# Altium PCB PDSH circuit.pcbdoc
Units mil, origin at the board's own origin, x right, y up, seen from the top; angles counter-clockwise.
Board outline 2980 x 2587.24 mil, 4 copper layers (Top Layer, Mid-Layer 1, Mid-Layer 2, Bottom Layer); 30 components, 20 nets, 87 pads, 24 vias.
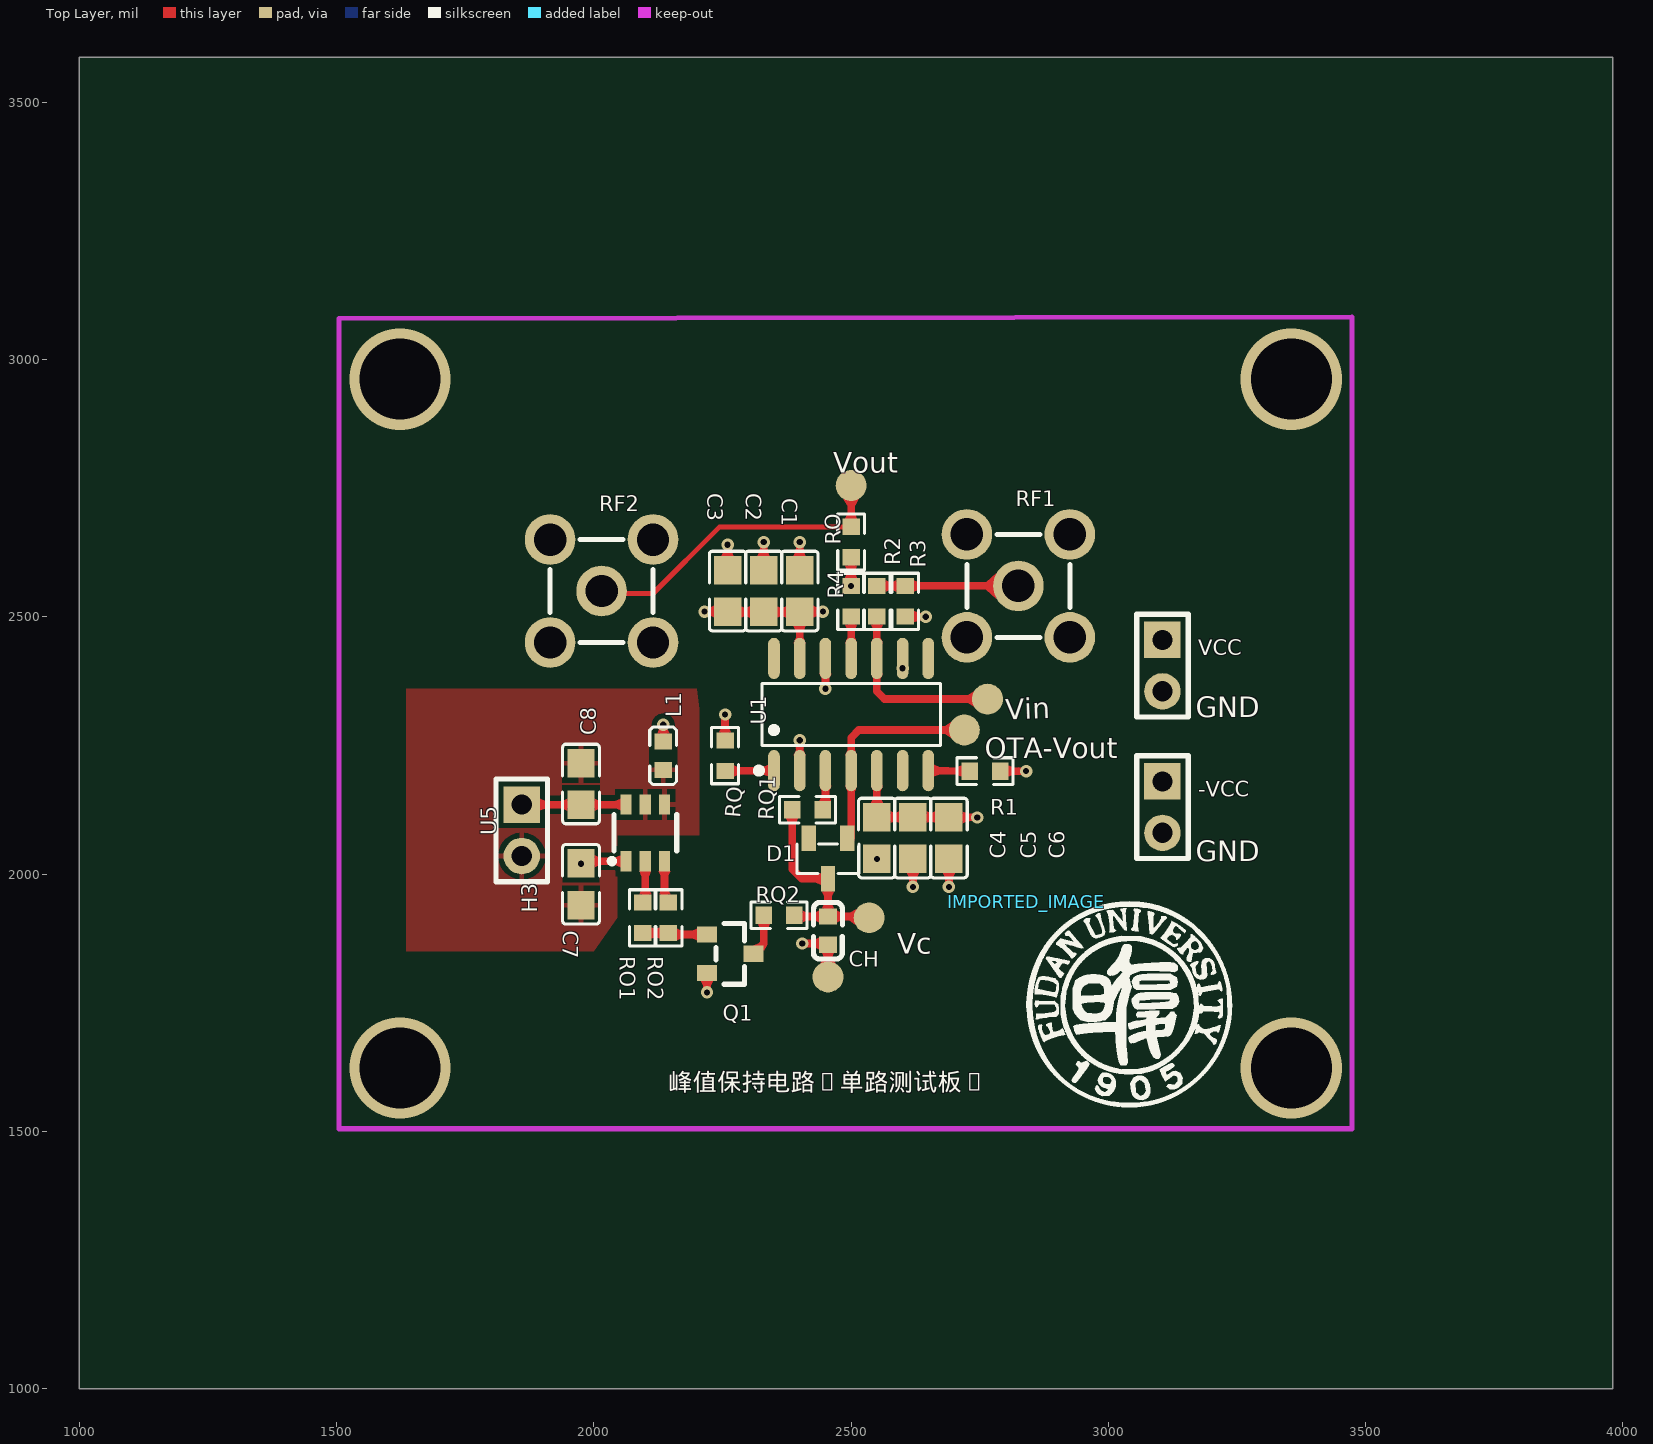
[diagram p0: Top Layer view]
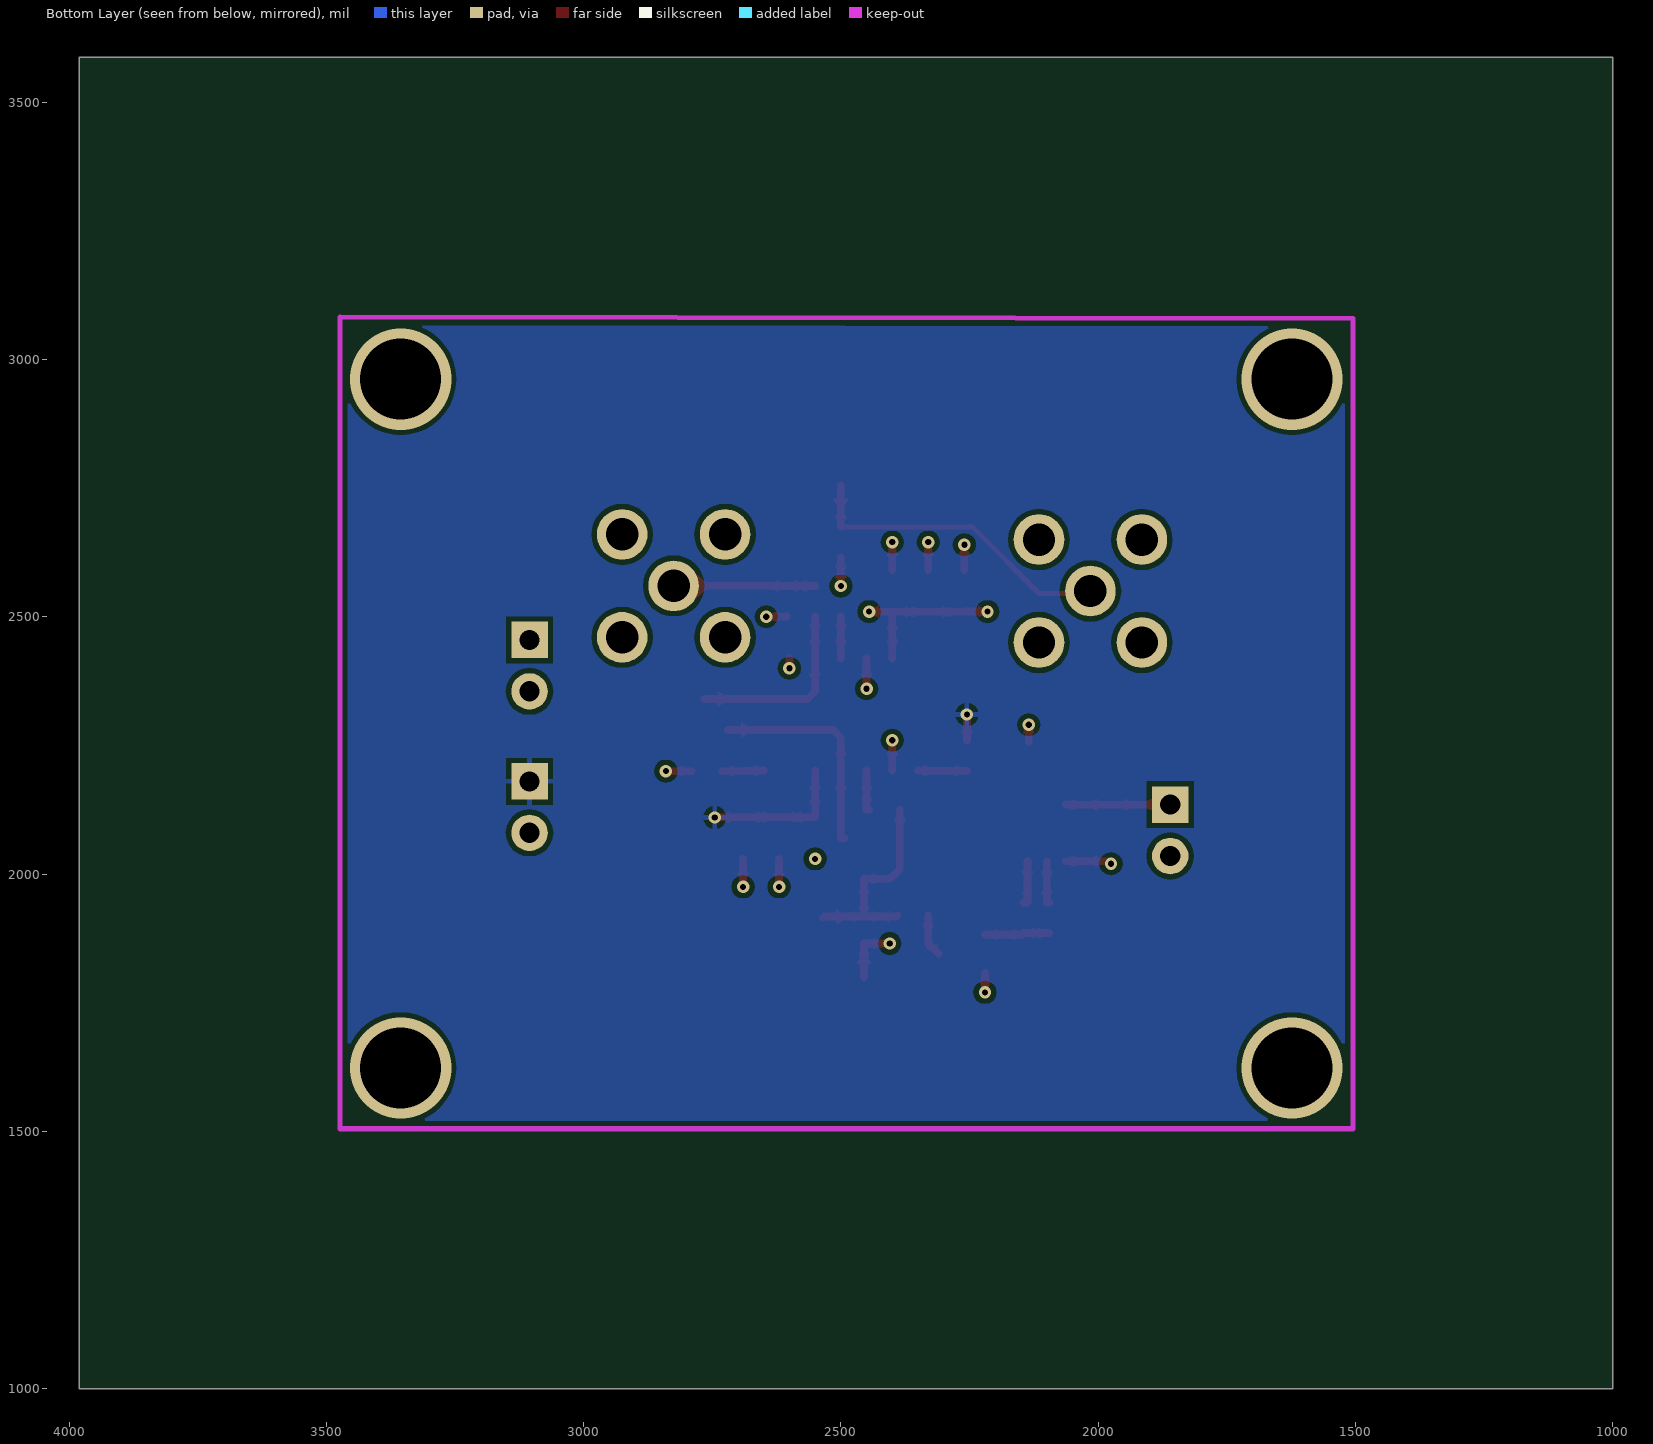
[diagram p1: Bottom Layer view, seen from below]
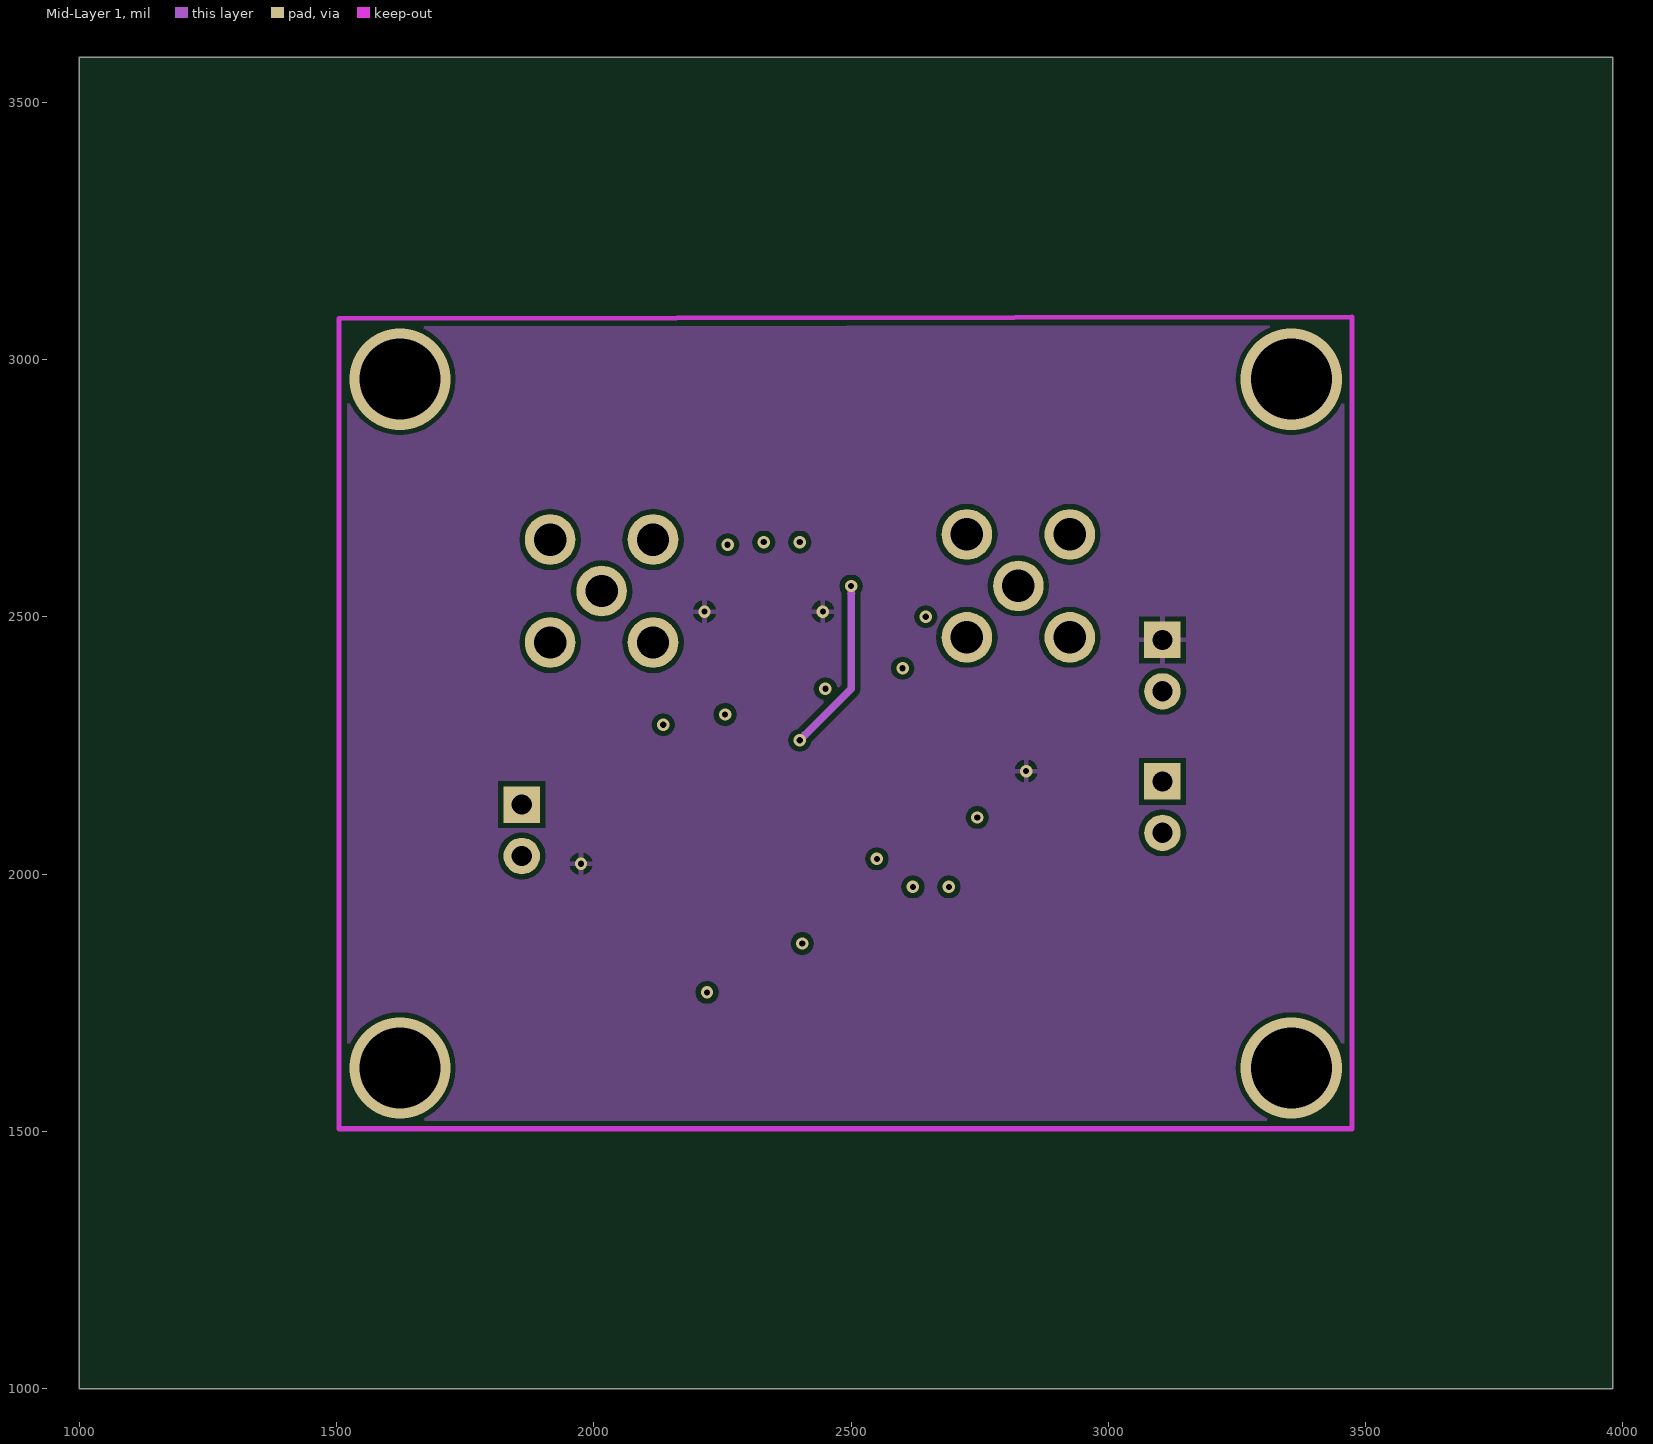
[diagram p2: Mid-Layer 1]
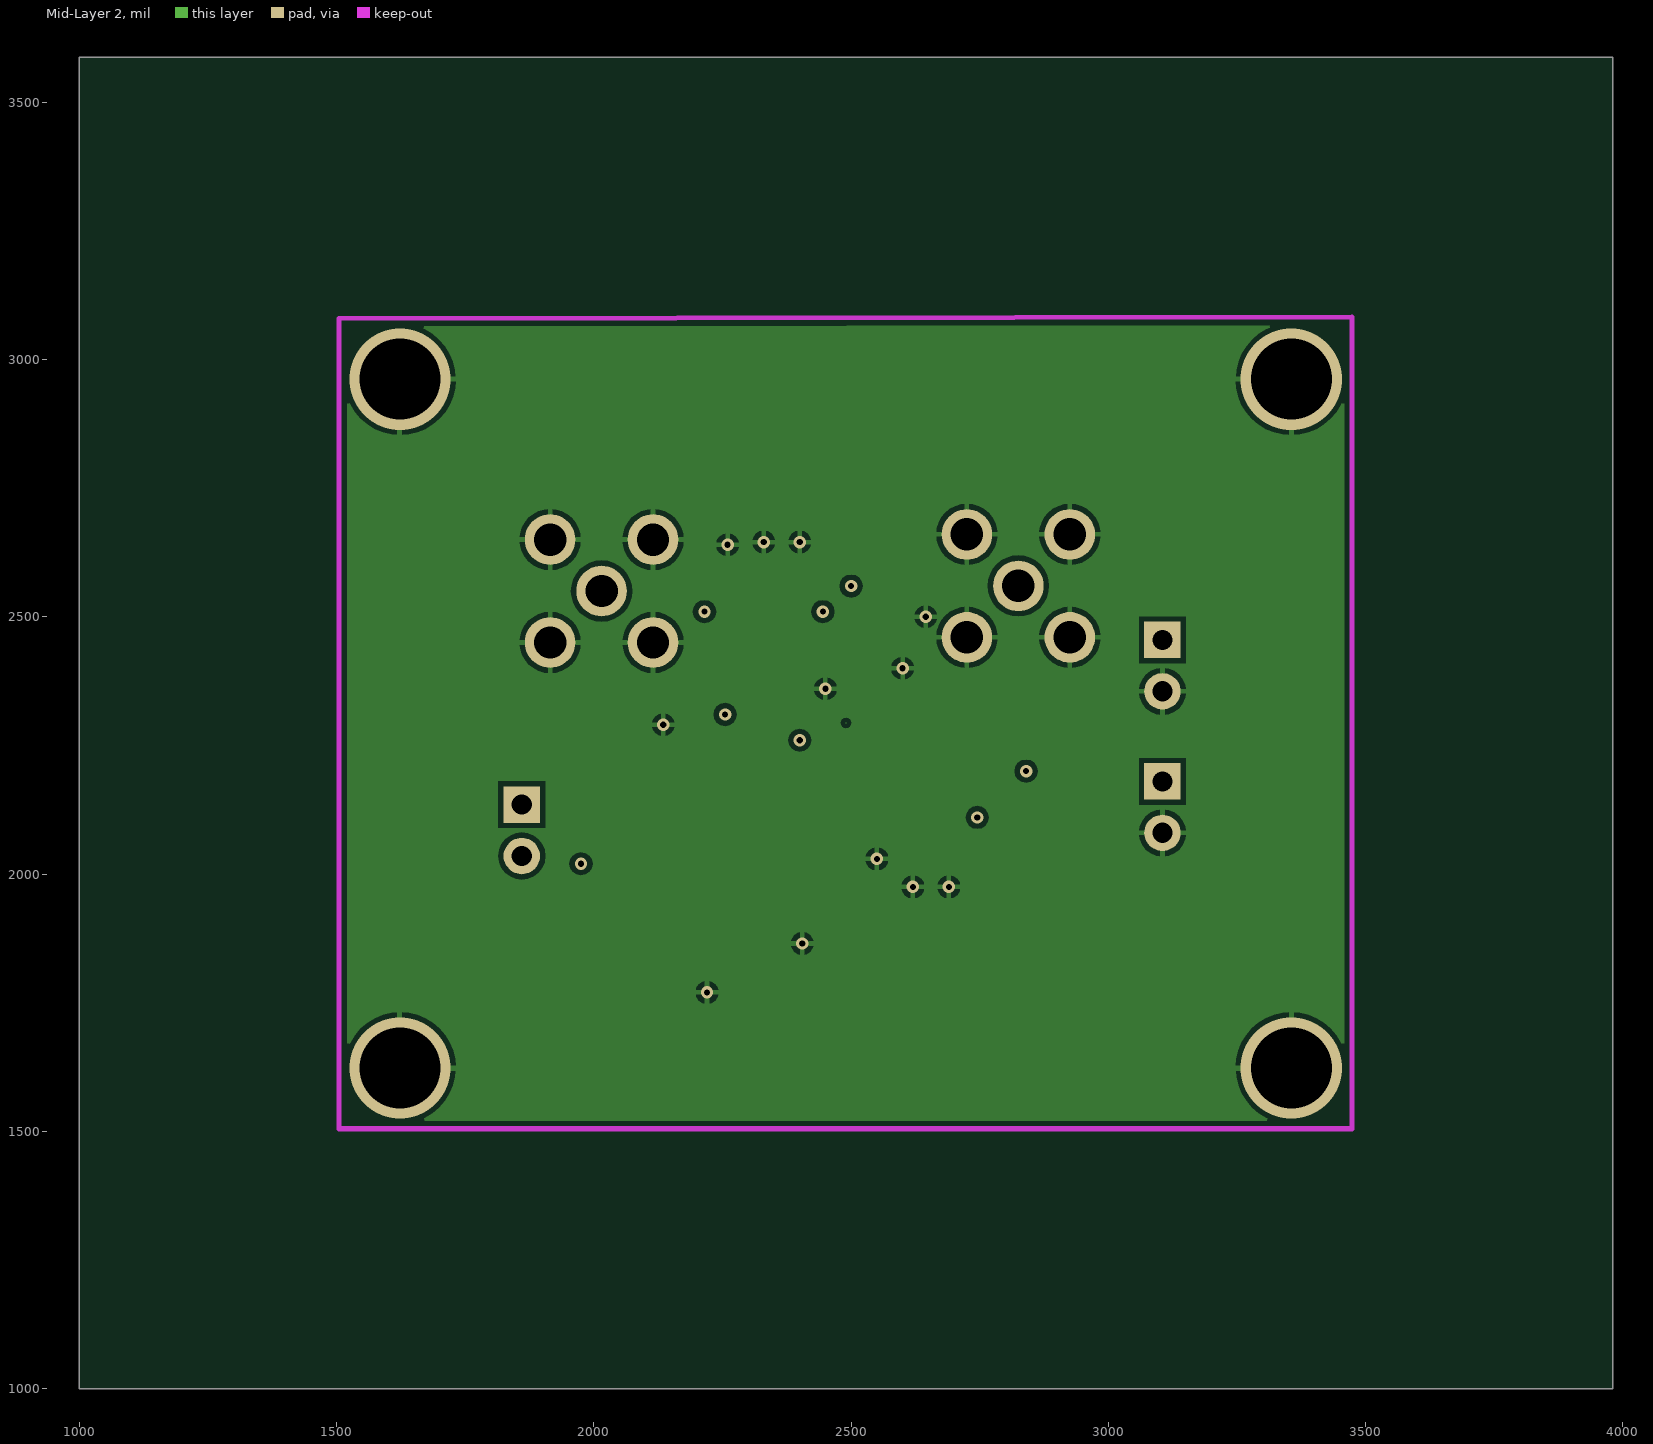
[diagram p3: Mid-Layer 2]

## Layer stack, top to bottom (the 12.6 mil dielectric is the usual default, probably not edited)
Top Solder: solder mask 0.4, Solder Resist, Dk 3.5
Top Layer: signal copper 1.4
Dielectric1: dielectric 12.6, FR-4, Dk 4.8
Mid-Layer 1: signal copper 1.4
Dielectric2: dielectric 12.6, FR-4, Dk 4.8
Mid-Layer 2: signal copper 1.4
Dielectric3: dielectric 12.6, FR-4, Dk 4.8
Bottom Layer: signal copper 1.4
Bottom Solder: solder mask 0.4, Solder Resist, Dk 3.5

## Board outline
3980,1000 1000,1000 1000,3587.24 3980,3587.24

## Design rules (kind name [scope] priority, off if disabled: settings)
Clearance [All] p1: gap=10 ignorepadtopadclearanceinfootprint=FALSE except(0: Arc-Hole Track-Hole SMDPad-Hole THPad-Hole Via-Hole Fill-Hole Poly-Hole Region-Hole Text-Hole)
PolygonConnect [All] p1: connectstyle=Relief reliefconductorwidth=10 reliefentries=4 polygonreliefangle="90 Angle" airgapwidth=10
RoutingVias [All] p1: holewidth=28 width=50 viastyle="Through Hole" minholewidth=28 minwidth=50 maxholewidth=28 maxwidth=50
SolderMaskExpansion [All] p1: expansion=4 istentingtop=FALSE
Width [All] p1: maxlimit=10 minlimit=10 preferedwidth=10
30 further rules are at their usual default settings.

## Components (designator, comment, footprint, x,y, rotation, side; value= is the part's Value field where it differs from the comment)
-VCC "Header-Male-2.54_1x2" HDR-TH_2P-P2.54-V-M-1 3105,2130 r270 top
C1 "2.2u" C0805 2400,2550 r270 top
C2 "10n" C0805 2330,2550 r270 top
C3 "470p" C0805 2260,2550 r270 top
C4 "470p" C0805 2550,2070 r90 top
C5 "10n" C0805 2620,2070 r90 top
C6 "2.2u" C0805 2690,2070 r90 top
C7 "2.2u" C0805 1975,1980 r270 top
C8 "470pF" C0805 1975,2175 r270 top
CH "47pF" C0603 2455,1890 r90 top
D1 "HSMS-2812-TR1G" SOT-23-3_L2.9-W1.3-P1.90-LS2.4-BR 2455,2030 r90 top
H3 "Header-Male-2.54_1x2" HDR-TH_2P-P2.54-V-M-1 1860,2085 r270 top
IMPORTED_IMAGE "Comment" IMPORTED_IMAGE 2840.18,1946.47 r0 top
L1 "UPZ1608U220-6R0TF" L0603 2135,2230 r90 top
Q1 "L2N7002LT1G" SOT-23_L2.9-W1.3-P1.90-LS2.4-BR 2265,1845 r180 top
R1 "330" R0603 2760,2200 r180 top
R2 "100" R0603 2550,2530 r90 top
R3 "50" R0603 2605,2530 r90 top
R4 "330" R0603 2500,2530 r90 top
RF1 "KH-SMA-KE-Z" SMA-TH_KH-SMA-KE-Z 2825,2560 r0 top
RF2 "KH-SMA-KE-Z" SMA-TH_KH-SMA-KE-Z 2015,2550 r0 top
RO "50" R0603 2500,2645 r270 top
RO1 "1k" R0603 2095,1915 r90 top
RO2 "1k" R0603 2145,1915 r90 top
RQ "300" R0603 2255,2230 r270 top
RQ1 "300" R0603 2415,2125 r0 top
RQ2 "50" R0603 2360,1920 r180 top
U1 "OPA615IDR" SOIC-14_L8.7-W3.9-P1.27-LS6.0-BL 2500,2310 r0 top
U5 "SL27511" SOT-23-6_L2.9-W1.6-P0.95-LS2.8-BR 2100,2080 r270 top
VCC "Header-Male-2.54_1x2" HDR-TH_2P-P2.54-V-M-1 3105,2405 r270 top

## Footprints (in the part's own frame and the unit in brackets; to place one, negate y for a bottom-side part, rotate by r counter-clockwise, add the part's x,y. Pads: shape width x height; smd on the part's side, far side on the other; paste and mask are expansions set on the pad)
C0603 [mm]
  rect 0.8x0.9 smd paste+0 mask+0.051: 1(-0.7,0) 2(0.7,0)
  silkscreen extent -1.41,-0.71 1.39,0.72
C0805 [mm]
  rect 1.41x1.35 smd paste-100 mask+0.051: 1(-1.03,0) 2(1.03,0)
  silkscreen extent -1.96,-0.9 1.96,0.9
HDR-TH_2P-P2.54-V-M-1 [mm]
  rect 1.8x1.8 hole 1 paste+0 mask+0.051: 1(-1.27,0)
  round 1.8 hole 1 paste+0 mask+0.051: 2(1.27,0)
  silkscreen extent -2.54,-1.27 2.54,1.27
IMPORTED_IMAGE [mil]
  silkscreen extent 0,-400 400,0
L0603 [mm]
  rect 0.8x0.864 smd paste-100 mask+0.051: 1(-0.7,0) 2(0.7,0)
  silkscreen extent -1.42,-0.65 1.41,0.67
R0603 [mil]
  rect 31.75x34.02 smd paste-3937.01 mask+2: 1(-29.66,0) 2(29.66,0)
  silkscreen extent -55,-26 55,26
SMA-TH_KH-SMA-KE-Z [mm]
  round 2.5 hole 1.6 paste+0 mask+0.051: 1(-2.54,-2.54) 2(-2.54,2.54) 3(2.54,2.54) 4(2.54,-2.54) 5(0,0)
  silkscreen extent -2.54,-2.54 2.54,2.54
SOIC-14_L8.7-W3.9-P1.27-LS6.0-BL [mil]
  oval 22.6x80.24 smd paste+0 mask+2: 1(-150,-109.02) 2(-100,-109.02) 3(-50,-109.02) 4(0,-109.02) 5(50,-109.02) 6(100,-109.02) 7(150,-109.02) 8(150,109.01) 9(100,109.01) 10(50,109.01) 11(0,109.01) 12(-50,109.01) 13(-100,109.01) 14(-150,109.01)
  silkscreen extent -185,-115 173,60
SOT-23-3_L2.9-W1.3-P1.90-LS2.4-BR [mm]
  rect 1.25x0.7 smd paste+0 mask+0.051: 1(1,-0.95) 2(1,0.95) 3(-1,0)
  silkscreen extent -0.73,-1.53 0.73,1.53
SOT-23-6_L2.9-W1.6-P0.95-LS2.8-BR [mm]
  rect 1x0.55 smd paste+0 mask+0.051: 1(1.4,-0.95) 2(1.4,0) 3(1.4,0.95) 4(-1.4,0.95) 5(-1.4,0) 6(-1.4,-0.95)
  silkscreen extent -0.9,-1.78 1.52,1.55
SOT-23_L2.9-W1.3-P1.90-LS2.4-BR [mm]
  rect 1x0.8 smd paste+0 mask+0.051: 1(1.15,-0.95) 2(1.15,0.95) 3(-1.15,0)
  silkscreen extent -0.7,-1.5 0.7,1.5

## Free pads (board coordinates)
  round 60 smd paste+0 mask+1.97: 1(2455,1800) 1(2500,2755) 1(2535,1915) 1(2720,2280) 1(2765,2340)

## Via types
v1: diameter 24, hole 12, Top Layer to Bottom Layer, 20 vias
v2: diameter 196.85, hole 157.48, Top Layer to Bottom Layer, 4 vias

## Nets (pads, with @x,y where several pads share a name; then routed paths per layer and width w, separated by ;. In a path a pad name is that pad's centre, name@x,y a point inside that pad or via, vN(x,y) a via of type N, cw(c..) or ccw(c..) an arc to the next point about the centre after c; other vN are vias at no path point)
-VCC: -VCC.1 C4.2 C5.2 C6.2 RQ.1 U1.5 | length 335.8
  Top Layer w15: RQ.1 v1(2255,2310) ; U1.5 2550,2110.5 2620,2110.5 2690,2110.5 v1(2745,2110)
AGND: C7.2 C8.1 H3.2 L1.1 U5.4 U5.5
D1_2: CH.2 D1.3 pad.1@2535,1915 RQ1.1 RQ2.1 | length 413.3
  Top Layer w15: RQ1.1 2385.3,2009.7 2404.4,1990.6 D1.3 CH.2 ; RQ2.1 2392.1,1917.6 CH.2 ; pad.1@2535,1915 2532.4,1917.6 CH.2
GND: -VCC.2 C1.1 C2.1 C3.1 C4.1 C5.1 C6.1 CH.1 L1.2 pad.1@2455,1800 Q1.2 R3.1 RF1.1 RF1.2 RF1.3 RF1.4 RF2.1 RF2.2 RF2.3 RF2.4 U1.9 U1.12 VCC.2 | length 570.5
  Top Layer w15: L1.2 v1(2135,2290) ; Q1.2 v1(2220,1770) ; C3.1@2260,2590.5 v1(2260,2640) ; C2.1@2330,2590.5 v1(2330,2645) ; C1.1@2400,2590.5 v1(2400,2645) ; v1(2405,1865) 2455,1865 CH.1 pad.1@2455,1800 ; v1(2450,2360) U1.12 ; v1(2600,2400) U1.9 ; R3.1 v1(2645,2500) ; v1(2620,1975) C5.1@2620,2029.5 ; v1(2690,1975) C6.1@2690,2029.5
  other v1: 2550,2029.45
  other v2: 1623.11,1623.11 3355.39,1623.11 1623.11,2961.69 3355.39,2961.69
Q1_3: Q1.3 RQ2.2 | length 83.3
  Top Layer w15: Q1.3 2330.3,1865.1 RQ2.2
RO_1: pad.1@2500,2755 RF2.5 RO.1 | length 621.1
  Top Layer w10: RF2.5 2020,2545 2115,2545 2244.7,2674.7 RO.1
  Top Layer w15: RO.1 pad.1@2500,2755
S$1077: 
U1_1: RQ.2 U1.1 | length 95
  Top Layer w15: RQ.2 U1.1
U1_7: R1.2 U1.7 | length 80.3
  Top Layer w15: U1.7 R1.2
U1_10: pad.1@2765,2340 R2.1 U1.10 | length 366.5
  Top Layer w15: R2.1 U1.10 2550,2355 2565,2340 2670,2340 pad.1@2765,2340
U1_11: R4.1 U1.11 | length 81.3
  Top Layer w15: U1.11 R4.1
U5_2: RO1.2 U5.2 | length 85.2
  Top Layer w15: RO1.2 2100,1944.7 U5.2
U5_3: RO2.2 U5.3 | length 87.8
  Top Layer w15: U5.3 2137.4,1944.7 RO2.2
VC: RQ1.2 U1.3 | length 81.3
  Top Layer w15: RQ1.2 2450,2125 U1.3
VCC: C1.2 C2.2 C3.2 C7.1 R1.1 U1.13 U5.1 VCC.1 | length 461
  Top Layer w15: v1(1975,2020) 1975,2020.5 1979.3,2024.9 U5.1 ; v1(2215,2510) 2259.5,2510 2260,2509.5 2330,2509.5 C1.2@2400,2509.5 ; U1.13 C1.2@2400,2509.5 ; v1(2445,2510) C1.2@2400,2509.5 ; R1.1 v1(2840,2200)
VCONTROL: Q1.1 RO1.1 RO2.1 | length 125.9
  Top Layer w15: RO1.1 RO2.1 2147.9,1882.4 Q1.1
VFB: R4.2 RO.2 U1.2 | length 455.7
  Top Layer w15: U1.2 v1(2400,2260) ; v1(2500,2559.66) RO.2
  Mid-Layer 1 w15: v1(2400,2260) 2500,2360 v1(2500,2559.66)
VIN: R2.2 R3.2 RF1.5 | length 275
  Top Layer w15: R2.2 R3.2 RF1.5
VOUT: D1.1 pad.1@2720,2280 U1.4 | length 429.4
  Top Layer w15: D1.1 2500,2069.4 U1.4 2500,2265 2515,2280 pad.1@2720,2280
VTRIGGER: C8.2 H3.1 U5.6 | length 202.6
  Top Layer w15: H3.1 1975,2134.5 U5.6
pads on no net: D1.2 U1.6 U1.8 U1.14
copper on no net: | length 0

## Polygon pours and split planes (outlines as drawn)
-VCC on Bottom Layer "Bottom Layer--VCC" (solid, pour order 0): 1550,3080 1560,3080 3470,3080 3480,2300 3475,1915 3475,1535 3475,1505 1505,1505 1505,1575 1505,3070 1505,3080
GND on Mid-Layer 2 "Mid-Layer 2-GND" (solid, pour order 1): 1505,3075 1515,3085 3475,3085 3475,1515 3465,1505 1505,1505 1505,1635 1505,1755
VCC on Mid-Layer 1 "Mid-Layer 1-VCC" (solid, pour order 2): 1510,1505 1515,1510 1505,3080 3470,3080 3470,1505 1510,1505
AGND on Top Layer "Top Layer-AGND" (solid, pour order 3): 1635,2360 1705,2360 1955,2360 2200,2360 2205,2320 2205,2075 2110,2075 2045,2075 2045,1915 2000,1850 1670,1850 1635,1850 1635,1885 1635,2250 1635,2340

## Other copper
Top Layer:
  region net VOUT: 2694.02,2265 2694.02,2295 2682.02,2287.5 2682.02,2272.5
  region net U1_10: 2739.02,2325 2739.02,2355 2727.02,2347.5 2727.02,2332.5
  region net D1_2: 2510.09,1931.72 2508.07,1901.79 2496.6,1910.06 2497.61,1925.06
  region net RO_1: 2515,2729.02 2485,2729.02 2492.5,2717.02 2507.5,2717.02
  region net GND: 2470,1825.98 2440,1825.98 2447.5,1837.98 2462.5,1837.98
  region net VIN: 2782.41,2535.34 2782.35,2584.55 2762.69,2567.41 2762.71,2552.41
  region net VCC: 2225.39,2504 2225.39,2516 2230.19,2517.5 2230.19,2502.5
  region net VCC: 2434.68,2503.88 2434.54,2515.88 2429.73,2517.33 2429.89,2502.33
  region net VCC: 2829.61,2194 2829.61,2206 2824.81,2207.5 2824.81,2192.5
  region net GND: 2141,2279.61 2129,2279.61 2127.5,2274.81 2142.5,2274.81
  region net GND: 2225.92,1780.44 2213.92,1780.34 2212.38,1785.13 2227.38,1785.25
  region net GND: 2415.39,1859 2415.39,1871 2420.19,1872.5 2420.19,1857.5
  region net GND: 2456,2370.39 2444,2370.39 2442.5,2375.19 2457.5,2375.19
  region net GND: 2634.65,2506.08 2634.56,2494.08 2629.75,2492.61 2629.86,2507.61
  region net GND: 2266,2629.61 2254,2629.61 2252.5,2624.81 2267.5,2624.81
  region net GND: 2336,2634.61 2324,2634.61 2322.5,2629.81 2337.5,2629.81
  region net GND: 2406,2634.61 2394,2634.61 2392.5,2629.81 2407.5,2629.81
  region net VFB: 2406,2249.61 2394,2249.61 2392.5,2244.81 2407.5,2244.81
  region net VFB: 2506,2570.05 2494,2570.05 2492.5,2574.85 2507.5,2574.85
  region net GND: 2696,1985.39 2684,1985.39 2682.5,1990.19 2697.5,1990.19
  region net GND: 2626,1985.39 2614,1985.39 2612.5,1990.19 2627.5,1990.19
  region net -VCC: 2734.66,2116.09 2734.55,2104.09 2729.74,2102.64 2729.88,2117.64
  region net -VCC: 2261,2299.61 2249,2299.61 2247.5,2294.81 2262.5,2294.81
  region net VCC: 2373.42,2498.2 2373.42,2520.7 2364.42,2516.95 2364.42,2501.95
  region net VCC: 2426.58,2521.05 2426.58,2498.55 2435.58,2502.39 2435.58,2517.4
  region net VCC: 2411.25,2481.69 2388.75,2481.69 2392.5,2472.69 2407.5,2472.69
  region net GND: 2411.25,2618.31 2388.75,2618.31 2392.5,2627.31 2407.5,2627.31
  region net VCC: 2356.58,2520.7 2356.58,2498.2 2365.58,2501.95 2365.58,2516.95
  region net VCC: 2303.42,2498.2 2303.42,2520.7 2294.42,2516.95 2294.42,2501.95
  region net GND: 2341.25,2618.31 2318.75,2618.31 2322.5,2627.31 2337.5,2627.31
  region net VCC: 2286.58,2520.7 2286.58,2498.2 2295.58,2501.95 2295.58,2516.95
  region net VCC: 2233.43,2498.75 2233.43,2521.25 2224.43,2517.5 2224.43,2502.5
  region net GND: 2271.25,2618.31 2248.75,2618.31 2252.5,2627.31 2267.5,2627.31
  region net -VCC: 2538.75,2138.31 2561.25,2138.31 2557.5,2147.31 2542.5,2147.31
  region net -VCC: 2576.58,2121.8 2576.58,2099.3 2585.58,2103.05 2585.58,2118.05
  region net -VCC: 2593.42,2099.3 2593.42,2121.8 2584.42,2118.05 2584.42,2103.05
  region net -VCC: 2646.58,2121.8 2646.58,2099.3 2655.58,2103.05 2655.58,2118.05
  region net GND: 2608.75,2001.69 2631.25,2001.69 2627.5,1992.69 2612.5,1992.69
  region net -VCC: 2663.42,2099.3 2663.42,2121.8 2654.42,2118.05 2654.42,2103.05
  region net -VCC: 2716.58,2121.51 2716.58,2099.01 2725.58,2102.68 2725.58,2117.68
  region net GND: 2678.75,2001.69 2701.25,2001.69 2697.5,1992.69 2682.5,1992.69
  region net VCC: 2001.57,2013.63 2001.57,2036.13 2010.57,2032.38 2010.57,2017.38
  region net VTRIGGER: 1948.43,2123.33 1948.43,2145.83 1939.43,2142.12 1939.43,2127.12
  region net VTRIGGER: 2001.57,2145.9 2001.57,2123.4 2010.57,2127.22 2010.57,2142.22
  region net D1_2: 2472.71,1928.81 2472.71,1906.31 2481.71,1910.06 2481.71,1925.06
  region net D1_2: 2437.29,1906.31 2437.29,1928.81 2428.29,1925.06 2428.29,1910.06
  region net D1_2: 2443.75,1933.31 2466.25,1933.31 2462.5,1942.31 2447.5,1942.31
  region net GND: 2466.25,1846.69 2443.75,1846.69 2447.5,1837.69 2462.5,1837.69
  region net GND: 2437.29,1853.75 2437.29,1876.25 2428.29,1872.5 2428.29,1857.5
  region net D1_2: 2441.22,1979.38 2441.22,2001.88 2432.22,1998.13 2432.22,1983.13
  region net D1_2: 2466.25,1966.02 2443.75,1966.02 2447.5,1957.02 2462.5,1957.02
  region net VTRIGGER: 1895.43,2146.08 1895.43,2123.58 1904.43,2127.29 1904.43,2142.29
  region net GND: 2123.75,2273.31 2146.25,2273.31 2142.5,2282.31 2127.5,2282.31
  region net GND: 2231.08,1791.85 2208.58,1791.85 2212.4,1782.85 2227.4,1782.85
  region net Q1_3: 2309.51,1860.75 2329.96,1851.36 2334.89,1859 2320.35,1865.68
  region net VCONTROL: 2200.04,1871.15 2200.04,1893.65 2191.04,1889.9 2191.04,1874.9
  region net U1_7: 2714.47,2188.95 2714.47,2211.45 2705.47,2207.81 2705.47,2192.81
  region net VCC: 2805.53,2188.75 2805.53,2211.25 2814.53,2207.5 2814.53,2192.5
  region net VIN: 2567.01,2570.91 2567.01,2548.41 2576.01,2552.16 2576.01,2567.16
  region net U1_10: 2538.75,2484.47 2561.25,2484.47 2557.5,2475.47 2542.5,2475.47
  region net VIN: 2622.01,2570.97 2622.01,2548.47 2631.01,2552.24 2631.01,2567.24
  region net VIN: 2587.99,2548.41 2587.99,2570.91 2578.99,2567.16 2578.99,2552.16
  region net GND: 2622.01,2488.92 2622.01,2511.42 2631.01,2507.61 2631.01,2492.6
  region net VFB: 2488.75,2575.53 2511.25,2575.53 2507.5,2584.53 2492.5,2584.53
  region net U1_11: 2488.75,2484.47 2511.25,2484.47 2507.5,2475.47 2492.5,2475.47
  region net VFB: 2511.25,2599.47 2488.75,2599.47 2492.5,2590.47 2507.5,2590.47
  region net RO_1: 2511.25,2690.53 2488.75,2690.53 2492.5,2699.53 2507.5,2699.53
  region net U5_2: 2088.75,1960.53 2111.25,1960.53 2107.5,1969.53 2092.5,1969.53
  region net VCONTROL: 2112.01,1874.09 2112.01,1896.59 2121.01,1892.84 2121.01,1877.84
  region net U5_3: 2127.99,1960.53 2148.65,1960.53 2144.9,1969.53 2129.9,1969.53
  region net VCONTROL: 2127.99,1896.59 2127.99,1874.09 2118.99,1877.84 2118.99,1892.84
  region net VCONTROL: 2162.01,1871.15 2162.01,1893.65 2171.01,1889.9 2171.01,1874.9
  region net U1_1: 2272.01,2211.68 2272.01,2189.18 2281.01,2192.99 2281.01,2207.99
  region net -VCC: 2266.25,2275.53 2243.75,2275.53 2247.5,2284.53 2262.5,2284.53
  region net VC: 2438.75,2142.01 2460.53,2142.01 2457.5,2151.01 2442.5,2151.01
  region net D1_2: 2374.09,2107.99 2396.59,2107.99 2392.84,2098.99 2377.84,2098.99
  region net Q1_3: 2341.59,1902.99 2319.09,1902.99 2322.84,1893.99 2337.84,1893.99
  region net D1_2: 2405.53,1906.31 2405.53,1928.81 2414.53,1925.06 2414.53,1910.06
  region net U5_3: 2148.23,2005.2 2126.58,2005.2 2129.9,1996.2 2144.9,1996.2
  region net U5_2: 2110.83,2005.2 2089.17,2005.2 2092.5,1996.2 2107.5,1996.2
  region net VCC: 2051.77,2013.63 2051.77,2036.13 2042.77,2032.38 2042.77,2017.38
  region net VTRIGGER: 2051.77,2123.79 2051.77,2146.29 2042.77,2142.47 2042.77,2127.47
  region net U1_1: 2338.7,2189.67 2338.7,2212.17 2329.7,2208.35 2329.7,2193.35
  region net VFB: 2411.25,2230.85 2388.75,2230.85 2392.5,2239.85 2407.5,2239.85
  region net VC: 2461.25,2171.11 2438.75,2171.11 2442.5,2162.11 2457.5,2162.11
  region net VOUT: 2511.25,2171.11 2488.75,2171.11 2492.5,2162.11 2507.5,2162.11
  region net VOUT: 2511.25,2230.85 2488.75,2230.85 2492.5,2239.85 2507.5,2239.85
  region net -VCC: 2561.25,2171.11 2538.75,2171.11 2542.5,2162.11 2557.5,2162.11
  region net U1_7: 2661.3,2212.11 2661.3,2189.61 2670.3,2193.25 2670.3,2208.25
  region net VCC: 2411.25,2448.89 2388.75,2448.89 2392.5,2457.89 2407.5,2457.89
  region net GND: 2461.25,2389.15 2438.75,2389.15 2442.5,2380.15 2457.5,2380.15
  region net U1_11: 2511.25,2448.89 2488.75,2448.89 2492.5,2457.89 2507.5,2457.89
  region net U1_10: 2561.25,2448.89 2538.75,2448.89 2542.5,2457.89 2557.5,2457.89
  region net U1_10: 2561.25,2389.15 2538.75,2389.15 2542.5,2380.15 2557.5,2380.15
Mid-Layer 1:
  region net VFB: 2411.59,2263.11 2403.11,2271.59 2405.44,2276.05 2416.05,2265.44
  region net VFB: 2506,2549.27 2494,2549.27 2492.5,2544.47 2507.5,2544.47

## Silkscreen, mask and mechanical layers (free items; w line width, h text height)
Top Overlay:
  text "Vout" at 2465,2780 h40
  text "GND" at 3170,2305 h40
  text "Vin" at 2800.7,2300.01 h40 r2
  text "OTA-Vout" at 2760,2225 h40
  text "GND" at 3170,2025 h40
  text "Vc" at 2590,1845 h40
  text "峰值保持电路(单路测试板)" at 2144.61,1566.89 h60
